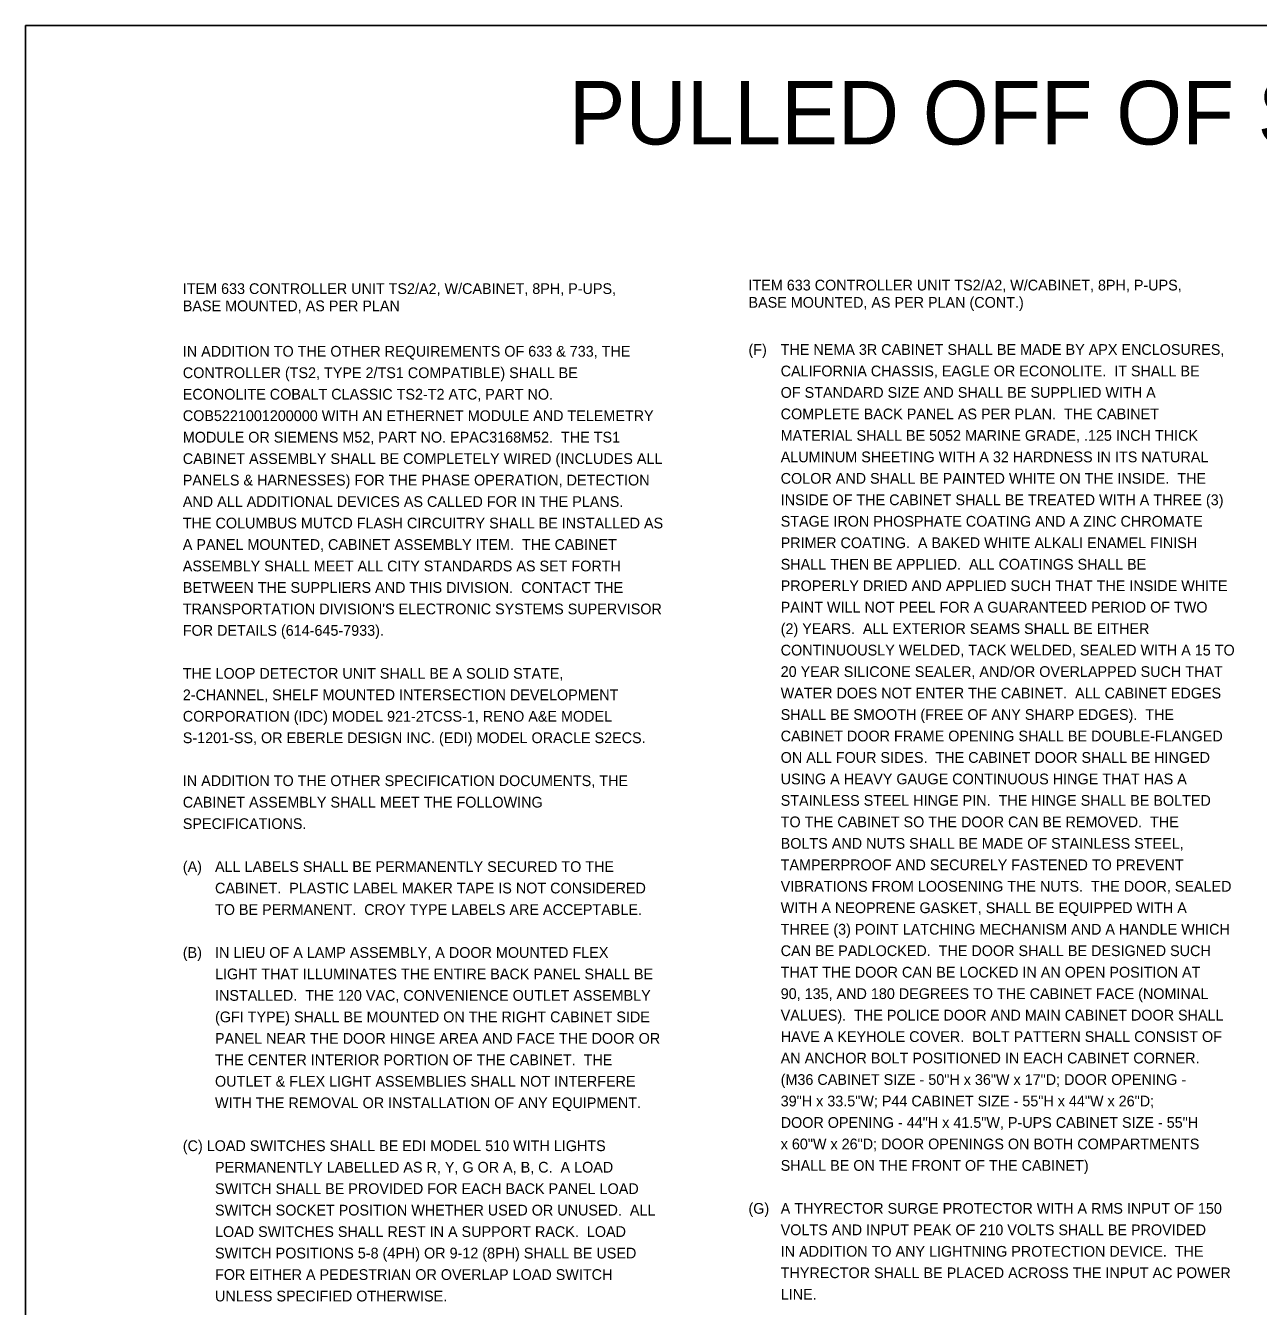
# Model space of a CAD drawing. Extents: x -27 to 74, y -37 to 38.
# Drawn here: x 42.58 to 58.66, y -19.99 to -3.29 of the extents above; entities that cross this region are included whole.
import ezdxf

# ---------------------------------------------------------------- set-up
doc = ezdxf.new("R2010")
doc.units = 0
doc.layers.add('SH_Data', color=7, linetype='Continuous')
doc.layers.add('SH_Text', color=7, linetype='Continuous')

msp = doc.modelspace()

# ---------------------------------------------------------------- linework, layer by layer
at = {"layer": 'SH_Text'}
msp.add_lwpolyline([(42.584, -3.293), (74.352, -3.293), (74.352, -36.623), (42.584, -36.623)], close=True, dxfattribs=at)

# ---------------------------------------------------------------- texts
at = {"layer": 'SH_Data'}
for s, height, p in [('PULLED OFF OF SHEET', 0.82794, (49.665, -4.843)), ('ITEM 633 CONTROLLER UNIT TS2/A2, W/CABINET, 8PH, P-UPS, ', 0.14, (44.633, -6.793)), ('ITEM 633 CONTROLLER UNIT TS2/A2, W/CABINET, 8PH, P-UPS, ', 0.14, (52.008, -6.747)), ('BASE MOUNTED, AS PER PLAN (CONT.)', 0.14, (52.008, -6.972)), ('BASE MOUNTED, AS PER PLAN', 0.14, (44.633, -7.018)), ('IN ADDITION TO THE OTHER REQUIREMENTS OF 633 & 733, THE ', 0.14, (44.633, -7.61)), ('(F)', 0.14, (52.008, -7.587)), ('THE NEMA 3R CABINET SHALL BE MADE BY APX ENCLOSURES, ', 0.14, (52.428, -7.587)), ('CONTROLLER (TS2, TYPE 2/TS1 COMPATIBLE) SHALL BE ', 0.14, (44.633, -7.89)), ('CALIFORNIA CHASSIS, EAGLE OR ECONOLITE.  IT SHALL BE ', 0.14, (52.428, -7.867)), ('OF STANDARD SIZE AND SHALL BE SUPPLIED WITH A ', 0.14, (52.428, -8.147)), ('ECONOLITE COBALT CLASSIC TS2-T2 ATC, PART NO. ', 0.14, (44.633, -8.17)), ('COB5221001200000 WITH AN ETHERNET MODULE AND TELEMETRY ', 0.14, (44.633, -8.45)), ('COMPLETE BACK PANEL AS PER PLAN.  THE CABINET ', 0.14, (52.428, -8.427)), ('MODULE OR SIEMENS M52, PART NO. EPAC3168M52.  THE TS1 ', 0.14, (44.633, -8.73)), ('MATERIAL SHALL BE 5052 MARINE GRADE, .125 INCH THICK ', 0.14, (52.428, -8.707)), ('ALUMINUM SHEETING WITH A 32 HARDNESS IN ITS NATURAL ', 0.14, (52.428, -8.987)), ('CABINET ASSEMBLY SHALL BE COMPLETELY WIRED (INCLUDES ALL ', 0.14, (44.633, -9.01)), ('PANELS & HARNESSES) FOR THE PHASE OPERATION, DETECTION ', 0.14, (44.633, -9.29)), ('COLOR AND SHALL BE PAINTED WHITE ON THE INSIDE.  THE ', 0.14, (52.428, -9.267)), ('AND ALL ADDITIONAL DEVICES AS CALLED FOR IN THE PLANS.  ', 0.14, (44.633, -9.57)), ('INSIDE OF THE CABINET SHALL BE TREATED WITH A THREE (3) ', 0.14, (52.428, -9.547)), ('STAGE IRON PHOSPHATE COATING AND A ZINC CHROMATE ', 0.14, (52.428, -9.827)), ('THE COLUMBUS MUTCD FLASH CIRCUITRY SHALL BE INSTALLED AS ', 0.14, (44.633, -9.85)), ('A PANEL MOUNTED, CABINET ASSEMBLY ITEM.  THE CABINET ', 0.14, (44.633, -10.13)), ('PRIMER COATING.  A BAKED WHITE ALKALI ENAMEL FINISH ', 0.14, (52.428, -10.107)), ('ASSEMBLY SHALL MEET ALL CITY STANDARDS AS SET FORTH ', 0.14, (44.633, -10.41)), ('SHALL THEN BE APPLIED.  ALL COATINGS SHALL BE ', 0.14, (52.428, -10.387)), ('BETWEEN THE SUPPLIERS AND THIS DIVISION.  CONTACT THE ', 0.14, (44.633, -10.69)), ('PROPERLY DRIED AND APPLIED SUCH THAT THE INSIDE WHITE ', 0.14, (52.428, -10.667)), ("TRANSPORTATION DIVISION'S ELECTRONIC SYSTEMS SUPERVISOR ", 0.14, (44.633, -10.97)), ('PAINT WILL NOT PEEL FOR A GUARANTEED PERIOD OF TWO ', 0.14, (52.428, -10.947)), ('FOR DETAILS (614-645-7933).', 0.14, (44.633, -11.25)), ('(2) YEARS.  ALL EXTERIOR SEAMS SHALL BE EITHER ', 0.14, (52.428, -11.227)), ('CONTINUOUSLY WELDED, TACK WELDED, SEALED WITH A 15 TO ', 0.14, (52.428, -11.507)), ('THE LOOP DETECTOR UNIT SHALL BE A SOLID STATE, ', 0.14, (44.633, -11.81)), ('20 YEAR SILICONE SEALER, AND/OR OVERLAPPED SUCH THAT ', 0.14, (52.428, -11.787)), ('2-CHANNEL, SHELF MOUNTED INTERSECTION DEVELOPMENT ', 0.14, (44.633, -12.09)), ('WATER DOES NOT ENTER THE CABINET.  ALL CABINET EDGES ', 0.14, (52.428, -12.067)), ('CORPORATION (IDC) MODEL 921-2TCSS-1, RENO A&E MODEL   ', 0.14, (44.633, -12.37)), ('SHALL BE SMOOTH (FREE OF ANY SHARP EDGES).  THE ', 0.14, (52.428, -12.347)), ('S-1201-SS, OR EBERLE DESIGN INC. (EDI) MODEL ORACLE S2ECS.', 0.14, (44.633, -12.65)), ('CABINET DOOR FRAME OPENING SHALL BE DOUBLE-FLANGED ', 0.14, (52.428, -12.627)), ('ON ALL FOUR SIDES.  THE CABINET DOOR SHALL BE HINGED ', 0.14, (52.428, -12.907)), ('IN ADDITION TO THE OTHER SPECIFICATION DOCUMENTS, THE ', 0.14, (44.633, -13.21)), ('USING A HEAVY GAUGE CONTINUOUS HINGE THAT HAS A ', 0.14, (52.428, -13.187)), ('CABINET ASSEMBLY SHALL MEET THE FOLLOWING ', 0.14, (44.633, -13.49)), ('STAINLESS STEEL HINGE PIN.  THE HINGE SHALL BE BOLTED ', 0.14, (52.428, -13.467)), ('SPECIFICATIONS.', 0.14, (44.633, -13.77)), ('TO THE CABINET SO THE DOOR CAN BE REMOVED.  THE ', 0.14, (52.428, -13.747)), ('BOLTS AND NUTS SHALL BE MADE OF STAINLESS STEEL, ', 0.14, (52.428, -14.027)), ('(A)', 0.14, (44.633, -14.33)), ('ALL LABELS SHALL BE PERMANENTLY SECURED TO THE ', 0.14, (45.053, -14.33)), ('TAMPERPROOF AND SECURELY FASTENED TO PREVENT ', 0.14, (52.428, -14.307)), ('CABINET.  PLASTIC LABEL MAKER TAPE IS NOT CONSIDERED ', 0.14, (45.053, -14.61)), ('VIBRATIONS FROM LOOSENING THE NUTS.  THE DOOR, SEALED ', 0.14, (52.428, -14.587)), ('TO BE PERMANENT.  CROY TYPE LABELS ARE ACCEPTABLE.', 0.14, (45.053, -14.89)), ('WITH A NEOPRENE GASKET, SHALL BE EQUIPPED WITH A ', 0.14, (52.428, -14.867)), ('THREE (3) POINT LATCHING MECHANISM AND A HANDLE WHICH ', 0.14, (52.428, -15.147)), ('(B)', 0.14, (44.633, -15.45)), ('IN LIEU OF A LAMP ASSEMBLY, A DOOR MOUNTED FLEX ', 0.14, (45.053, -15.45)), ('CAN BE PADLOCKED.  THE DOOR SHALL BE DESIGNED SUCH ', 0.14, (52.428, -15.427)), ('LIGHT THAT ILLUMINATES THE ENTIRE BACK PANEL SHALL BE ', 0.14, (45.053, -15.73)), ('THAT THE DOOR CAN BE LOCKED IN AN OPEN POSITION AT ', 0.14, (52.428, -15.707)), ('90, 135, AND 180 DEGREES TO THE CABINET FACE (NOMINAL ', 0.14, (52.428, -15.987)), ('INSTALLED.  THE 120 VAC, CONVENIENCE OUTLET ASSEMBLY ', 0.14, (45.053, -16.01)), ('(GFI TYPE) SHALL BE MOUNTED ON THE RIGHT CABINET SIDE ', 0.14, (45.053, -16.29)), ('VALUES).  THE POLICE DOOR AND MAIN CABINET DOOR SHALL ', 0.14, (52.428, -16.267)), ('PANEL NEAR THE DOOR HINGE AREA AND FACE THE DOOR OR ', 0.14, (45.053, -16.57)), ('HAVE A KEYHOLE COVER.  BOLT PATTERN SHALL CONSIST OF ', 0.14, (52.428, -16.547)), ('AN ANCHOR BOLT POSITIONED IN EACH CABINET CORNER.  ', 0.14, (52.428, -16.827)), ('THE CENTER INTERIOR PORTION OF THE CABINET.  THE ', 0.14, (45.053, -16.85)), ('OUTLET & FLEX LIGHT ASSEMBLIES SHALL NOT INTERFERE ', 0.14, (45.053, -17.13)), ('(M36 CABINET SIZE - 50"H x 36"W x 17"D; DOOR OPENING - ', 0.14, (52.428, -17.107)), ('WITH THE REMOVAL OR INSTALLATION OF ANY EQUIPMENT.', 0.14, (45.053, -17.41)), ('39"H x 33.5"W; P44 CABINET SIZE - 55"H x 44"W x 26"D; ', 0.14, (52.428, -17.387)), ('DOOR OPENING - 44"H x 41.5"W, P-UPS CABINET SIZE - 55"H ', 0.14, (52.428, -17.667)), ('(C) LOAD SWITCHES SHALL BE EDI MODEL 510 WITH LIGHTS ', 0.14, (44.633, -17.97)), ('x 60"W x 26"D; DOOR OPENINGS ON BOTH COMPARTMENTS ', 0.14, (52.428, -17.947)), ('PERMANENTLY LABELLED AS R, Y, G OR A, B, C.  A LOAD ', 0.14, (45.053, -18.25)), ('SHALL BE ON THE FRONT OF THE CABINET)', 0.14, (52.428, -18.227)), ('SWITCH SHALL BE PROVIDED FOR EACH BACK PANEL LOAD ', 0.14, (45.053, -18.53)), ('SWITCH SOCKET POSITION WHETHER USED OR UNUSED.  ALL ', 0.14, (45.053, -18.81)), ('(G)', 0.14, (52.008, -18.787)), ('A THYRECTOR SURGE PROTECTOR WITH A RMS INPUT OF 150 ', 0.14, (52.428, -18.787)), ('LOAD SWITCHES SHALL REST IN A SUPPORT RACK.  LOAD ', 0.14, (45.053, -19.09)), ('VOLTS AND INPUT PEAK OF 210 VOLTS SHALL BE PROVIDED ', 0.14, (52.428, -19.067)), ('IN ADDITION TO ANY LIGHTNING PROTECTION DEVICE.  THE ', 0.14, (52.428, -19.347)), ('SWITCH POSITIONS 5-8 (4PH) OR 9-12 (8PH) SHALL BE USED ', 0.14, (45.053, -19.37)), ('FOR EITHER A PEDESTRIAN OR OVERLAP LOAD SWITCH ', 0.14, (45.053, -19.65)), ('THYRECTOR SHALL BE PLACED ACROSS THE INPUT AC POWER ', 0.14, (52.428, -19.627)), ('UNLESS SPECIFIED OTHERWISE.', 0.14, (45.053, -19.93)), ('LINE.', 0.14, (52.428, -19.907))]:
    msp.add_text(s, height=height, dxfattribs=at).set_placement(p)

doc.saveas('drawing.dxf')
